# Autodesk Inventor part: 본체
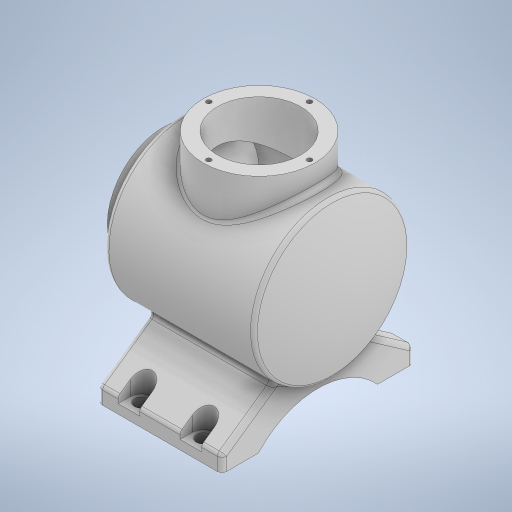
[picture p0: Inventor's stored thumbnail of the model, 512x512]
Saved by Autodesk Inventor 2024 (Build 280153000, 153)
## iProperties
Created: 2023-08
Part Number: 본체
Material: 일반
Document SubType Name: Modeling
Designer: Owner
Density: 1 g/cm^3
Appearance: 기본값
Author: Owner
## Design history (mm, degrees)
sketch "스케치1"
  geometry: L1 (-60, 0)-(60, 0); L2 (-48, 50)-(48.336, 50); L3 (-60, 0)-(-60, 36); L4 (-48, 36)-(-48, 50); L5 (-60, 36)-(-48, 36); A1 r 113 centre (-53, 0) between (60, 0) and (48.336, 50); 2 further points
  constraints: 12 end point, 3 horizontal, 2 point on circle, 2 vertical, 1 centre point, 1 coincident, 1 midpoint, 1 point on line
  dimensions: "d1" = 100 diameter of L2 L1; "d4" = 72 diameter of L5 L1; "d5" = 120 horizontal distance of L1.end L3.end; "d6" = 108 horizontal distance of L1.end L2.start; "d9" = 113 radius of A1
revolve "회전1" sketch "스케치1" stored, may be unused: angle "d10" = 90 deg
node "작업 평면1"
sketch "스케치2"
  geometry: L1 (60, 36)-(60, -36) reference; C1 r 36 at (-2, 0); 1 further point
  constraints: 1 centre point, 1 horizontal alignment
  dimensions: "d12" = 72 diameter of C1; "d13" = 62 distance from line of C1.centre L1
extrude "돌출1" join sketch "스케치2" stored distance "d14" = 10; taper "d15" = 0 deg
sketch "스케치4"
  geometry: L1 (-60, 27)-(-41, 27); L2 (-60, 0)-(-60, 27); L3 (-60, 0)-(53, 0); L4 (-60, -36)-(-60, 36) reference; L5 (-41, 27)-(-41, 43); L6 (-48, 50)-(48.336, 50) reference; L7 (-41, 43)-(43.887, 43); A1 r 113 centre (-53, 0) between (48.336, -50) and (48.336, 50) reference; A2 r 106 centre (-53, 0) between (53, 0) and (43.887, 43); 2 further points
  constraints: 10 end point, 2 point on circle, 2 vertical, 1 centre point, 1 horizontal, 1 horizontal alignment, 1 midpoint, 1 parallel, 1 point on line
  dimensions: "d31" = 19 distance of L1.start L1.end; "d32" = 54 diameter of L1 L3; "d34" = 7 distance between parallel lines of L6 L7; "d35" = 7 radial gap between concentric circles of A1 A2
revolve "회전3" sketch "스케치4" stored, may be unused: angle "d36" = 90 deg
sketch "스케치5"
  geometry: C1 r 36 at (0, 0) reference; C2 r 27 at (0, 0); 1 further point
  constraints: 1 centre point, 1 coincident
  dimensions: "d37" = 54 diameter of C2
extrude "돌출2" cut sketch "스케치5" stored distance "d38" = 10; taper "d39" = 0 deg
node "작업 평면5"
  node "작업 평면4"
sketch "스케치6"
  geometry: L1 (-67, -62)-(-77, -62); L2 (-77, 62)-(-67, 62); L3 (-77, -62)-(-77, -38.5); L4 (-77, 38.5)-(-77, 62); L5 (-67, -62)-(-42.278, -26.694); L6 (-67, 62)-(-42.278, 26.694); A1 r 52.096 centre (-112.096, 0) between (-77, -38.5) and (-77, 38.5); A2 r 50 centre (0, 0) between (-42.278, -26.694) and (-42.278, 26.694) reference; 3 further points
  constraints: 12 end point, 5 point on circle, 2 equal length, 2 horizontal, 1 centre point, 1 collinear, 1 horizontal alignment, 1 midpoint, 1 vertical, 1 vertical alignment
  dimensions: "d42" = 77 distance of L4.start L3.end; "d43" = 10 distance of L2.start L2.end; "d44" = 77 distance from line of point (0, 0) L4; "d45" = 17 horizontal distance of L4.start point (-60, 0); "d46" = 55 deg angle of L6 L2; "d78" = 124 vertical distance of L2.start point (-72, -62)
extrude "돌출3" join sketch "스케치6" stored distance "d47" = 80; taper "d48" = 0 deg
sketch "스케치8"
  geometry: 2 further points
  constraints: 1 vertical alignment
  dimensions: "d49" = 32.5 distance of point (0, 0) point (0, 32.5)
hole "구멍1" sketch "스케치8" at (0, 32.5) diameter "d50" = 3.242; stored, may be unused: countersink angle "d54" = 90 deg, drill point angle "d56" = 118 deg; dims "d51" = 8, "d52" = 4, "d53" = 2, "d55" = 10
sketch "스케치9"
  geometry: C1 r 27 at (0, 0) reference; 2 further points
  constraints: 1 vertical alignment
  dimensions: "d60" = 32.5 distance of C1.centre point (0, 32.5)
hole "구멍2" sketch "스케치9" at (0, 32.5) diameter "d61" = 3.242; stored, may be unused: countersink angle "d65" = 90 deg, drill point angle "d67" = 118 deg; dims "d62" = 8, "d63" = 4, "d64" = 2, "d66" = 10
node "작업 평면7"
  node "작업 평면6"
sketch "스케치10"
  geometry: L1 (40, -62)-(-40, -62) reference; L2 (-40, -38.5)-(-40, 38.5) reference; L3 (-27, -54)-(-27, -62); L4 (-13, -54)-(-13, -62); A1 r 7 centre (-20, -54) between (-13, -54) and (-27, -54); 1 further point
  constraints: 4 end point, 2 perpendicular, 2 point on circle, 2 point on line, 2 tangent, 1 centre point
  dimensions: "d73" = 14 diameter of A1; "d74" = 8 distance from line of A1.centre L1; "d75" = 20 distance from line of A1.centre L2
extrude "돌출4" cut sketch "스케치10" distance "d76" = 22; taper "d77" = 0 deg
sketch "스케치11"
  geometry: 1 further point
sketch "스케치12"
  geometry: C1 r 4.5 at (20, 54); A1 r 7 centre (20, 54) between (13, 54) and (27, 54) reference; 1 further point
  constraints: 1 centre point, 1 concentric
  dimensions: "d79" = 9 diameter of C1
extrude "돌출5" cut sketch "스케치12" extent not by distance; stored distance "d80" = 0; taper "d81" = 0 deg
fillet "모깎기1" dims "d85" = 3
fillet "모깎기2" dims "d86" = 3
fillet "모깎기3" dims "d87" = 3
feature "˨耀˪耀ˬ耀ˮ耀˰耀˲耀˴耀˶耀" dims "d1" = 100, "d4" = 72, "d5" = 120, "d6" = 108, "d9" = 113, "d10" = 90 deg, "d11" = 65, "d12" = 72, "d13" = 62, "d14" = 10, "d15" = 0, "d31" = 19, "d32" = 54, "d34" = 7, "d35" = 7, "d36" = 90 deg, "d37" = 54, "d38" = 10, "d39" = 0, "d40" = -60, "d41" = 60, "d42" = 77, "d43" = 10, "d44" = 77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
feature "̕耀̗耀̙耀̛耀̝耀̟耀̡耀̣耀" dims "d1" = 100, "d4" = 72, "d5" = 120, "d6" = 108, "d9" = 113, "d10" = 90 deg, "d11" = 65, "d12" = 72, "d13" = 62, "d14" = 10, "d15" = 0, "d31" = 19, "d32" = 54, "d34" = 7, "d35" = 7, "d36" = 90 deg, "d37" = 54, "d38" = 10, "d39" = 0, "d40" = -60, "d41" = 60, "d42" = 77, "d43" = 10, "d44" = 77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
node "솔리드1"
pattern_circular "원형 패턴1" dims angle "d58" = 360 deg
pattern_circular "원형 패턴2" dims angle "d69" = 360 deg
pattern_linear "직사각형 패턴1" dims "d84" = 40
mirror "미러1"
feature "A9D066F2-1C7D-4E18-AEED-F7BC21143FA4" dims "d50" = 3.242, "d51" = 8, "d52" = 4, "d53" = 2, "d54" = 90 deg, "d55" = 10, "d56" = 118 deg
